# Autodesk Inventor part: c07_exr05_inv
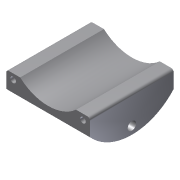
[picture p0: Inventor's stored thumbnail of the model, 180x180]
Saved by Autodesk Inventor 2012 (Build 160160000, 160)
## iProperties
Created: 2010-07
Part Number: c07_exr05_inv
Document SubType Name: Modeling
Designer: CADSoft
Density: 1 g/cm^3
Material: Default
Author: CADSoft
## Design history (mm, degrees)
sketch "Sketch1"
  geometry: 1 further point
sketch "Sketch2"
  geometry: L1 (-150, 60)-(150, 60); L2 (150, 60)-(150, 0); L3 (-150, 0)-(-150, 60); A1 r 200 centre (0, 132.288) between (-150, 0) and (150, 0); 1 further point
  constraints: 6 end point, 2 point on circle, 1 centre point, 1 horizontal, 1 horizontal alignment, 1 parallel, 1 perpendicular
  dimensions: "d0" = 60 distance of L3.start L1.start; "d1" = 300 distance of L1.start L1.end; "d2" = 150 distance from line of point (0, 0) L3; "d3" = 200 radius of A1
extrude "Extrusion1" new body sketch "Sketch2" stored distance "d5" = 300; taper "d6" = 0 deg
sketch "Sketch3"
  geometry: L1 (100, 60)-(-100, 60); L2 (-150, 60)-(150, 60) reference; A1 r 150 centre (0, 171.803) between (-100, 60) and (100, 60); 4 further points
  constraints: 2 end point, 2 midpoint, 2 point on circle, 2 vertical alignment, 1 centre point, 1 collinear, 1 horizontal, 1 horizontal alignment
  dimensions: "d7" = 150 radius of A1; "d8" = 200 distance of L1.end L1.start
extrude "Extrusion2" cut sketch "Sketch3" stored distance "d10" = 300; taper "d11" = 0 deg
fillet "Fillet1" dims "d12" = 10, "d13" = 10
hole "Hole1" diameter "d16" = 30; stored, may be unused: countersink angle "d20" = 90 deg, drill point angle "d22" = 118 deg; dims "d14" = 150, "d15" = 100, "d17" = 6, "d18" = 4, "d19" = 2, "d21" = 30
hole "Hole2" diameter "d25" = 20; stored, may be unused: countersink angle "d29" = 90 deg, drill point angle "d31" = 118 deg; dims "d23" = 20, "d24" = 25, "d26" = 6, "d27" = 4, "d28" = 2, "d30" = 30
mirror "Mirror1"
body "Solid1"
